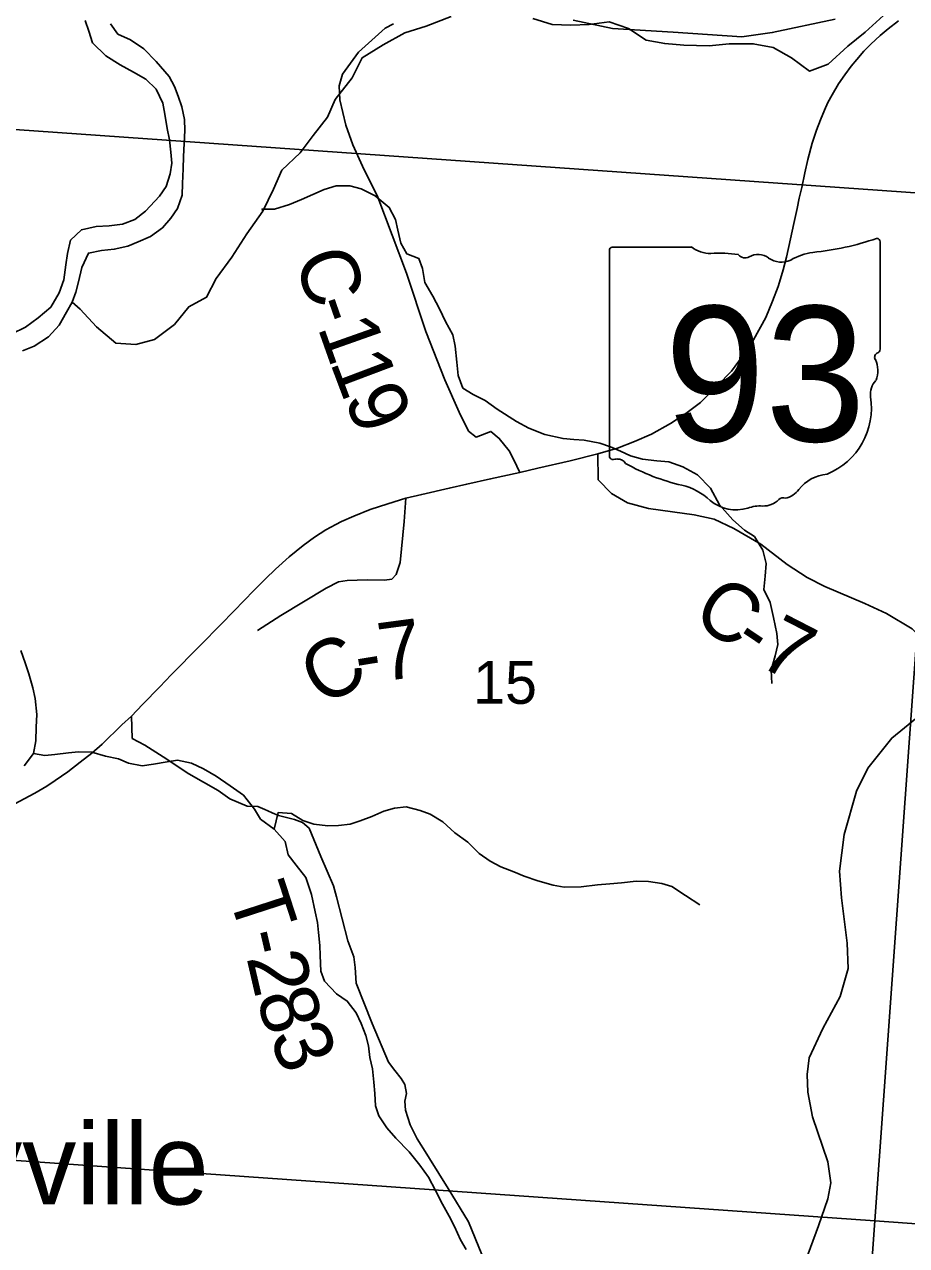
# Model space of a CAD drawing. Extents: x 0 to 34, y 0 to 22.
# Drawn here: x 3.78 to 4.64, y 16.363 to 17.554 of the extents above; entities that cross this region are included whole.
import ezdxf

# ---------------------------------------------------------------- set-up
doc = ezdxf.new("R2010")
doc.units = 0
for name, color, linetype in [('GM_X_Corporation', 7, 'Continuous'), ('GM_X_County_Road', 7, 'Continuous'), ('GM_X_County_Road_Text', 7, 'Continuous'), ('GM_X_Major_River', 7, 'Continuous'), ('GM_X_Minor_River', 7, 'Continuous'), ('GM_X_Section_Text', 7, 'Continuous'), ('GM_X_State_Location', 7, 'Continuous'), ('GM_X_State_Route', 7, 'Continuous'), ('GM_X_State_Shield', 7, 'Continuous'), ('GM_X_Township_Road', 7, 'Continuous'), ('GM_X_Township_Road_Text', 7, 'Continuous'), ('GM_X_Unincorporated_Text', 7, 'Continuous')]:
    doc.layers.add(name, color=color, linetype=linetype)

msp = doc.modelspace()

# ---------------------------------------------------------------- linework, layer by layer
at = {"layer": 'GM_X_Corporation'}
for points in [[(4.7598, 18.4308), (4.6804, 17.3872), (3.6641, 17.4586), (3.742, 18.4953)], [(3.6641, 17.4586), (4.6804, 17.3872), (4.6087, 16.3871), (3.6056, 16.4577)], [(4.6804, 17.3872), (5.6845, 17.321), (5.612, 16.3148), (5.6072, 16.3154), (4.6087, 16.3871)], [(4.6087, 16.3871), (4.5353, 15.3628), (3.5455, 15.4266), (3.6056, 16.4577)], [(4.6087, 16.3871), (5.6072, 16.3154), (5.5415, 15.2956), (4.5353, 15.3628)]]:
    msp.add_lwpolyline(points, close=True, dxfattribs=at)
at = {"layer": 'GM_X_County_Road'}
for points in [[(4.2627, 17.1168), (4.257, 17.1291), (4.2524, 17.1378), (4.2427, 17.15), (4.2346, 17.1567), (4.2201, 17.1513), (4.2127, 17.1571), (4.2036, 17.1755), (4.1895, 17.207), (4.1712, 17.2541), (4.1524, 17.3111), (4.1244, 17.385), (4.1095, 17.4154), (4.1001, 17.4361), (4.093, 17.4552), (4.0874, 17.48), (4.0866, 17.4937), (4.0899, 17.5051), (4.1055, 17.5264), (4.1314, 17.5498), (4.1395, 17.554)], [(4.3146, 17.5577), (4.3531, 17.5497), (4.4121, 17.5461), (4.4791, 17.5413), (4.5087, 17.5456), (4.57, 17.5588)], [(4.2627, 17.1168), (4.2802, 17.1208), (4.3117, 17.128), (4.3389, 17.135)], [(4.3389, 17.135), (4.339, 17.1096), (4.352, 17.0964), (4.3677, 17.087), (4.388, 17.0816), (4.4115, 17.0785), (4.4326, 17.0754), (4.4522, 17.0712), (4.4713, 17.062), (4.4975, 17.0467), (4.5233, 17.0271), (4.5427, 17.0142), (4.5599, 17.0055), (4.599, 16.9891), (4.62, 16.9791), (4.6451, 16.9642), (4.6614, 16.9475), (4.6713, 16.9325), (4.6755, 16.9179), (4.681, 16.9095), (4.6884, 16.9017), (4.6965, 16.8937)], [(4.1518, 17.0918), (4.1671, 17.0954), (4.194, 17.1014), (4.211, 17.1054), (4.2342, 17.1105), (4.2627, 17.1168)], [(4.0072, 16.9628), (4.0299, 16.9772), (4.0741, 17.0039), (4.086, 17.0102), (4.0943, 17.0115), (4.1141, 17.0122), (4.1307, 17.0119), (4.1379, 17.0128), (4.1422, 17.0173), (4.1462, 17.029), (4.1501, 17.0688), (4.1518, 17.0918)]]:
    msp.add_lwpolyline(points, dxfattribs=at)
at = {"layer": 'GM_X_Major_River'}
for points in [[(3.8392, 17.5575), (3.8426, 17.5469), (3.8464, 17.5355), (3.8592, 17.523), (3.8732, 17.5143), (3.8861, 17.5071), (3.8982, 17.5002), (3.9084, 17.4904), (3.9148, 17.4767), (3.9167, 17.4661), (3.919, 17.4521), (3.9212, 17.441), (3.9227, 17.4289), (3.9235, 17.4183), (3.922, 17.408), (3.9182, 17.3955), (3.9114, 17.386), (3.8978, 17.3716), (3.8876, 17.3632), (3.8755, 17.3587), (3.8626, 17.3571), (3.8498, 17.3564), (3.8354, 17.3533), (3.8248, 17.3431), (3.8218, 17.3302), (3.8203, 17.3192), (3.8184, 17.3047), (3.8138, 17.2918), (3.8055, 17.2778), (3.7934, 17.2675), (3.781, 17.2584), (3.7677, 17.252)], [(3.7779, 17.2353), (3.7893, 17.2398), (3.8033, 17.249), (3.8138, 17.2603), (3.821, 17.2729), (3.8263, 17.2827), (3.8301, 17.2926), (3.8327, 17.3025), (3.8358, 17.3165), (3.8422, 17.3306), (3.8551, 17.3332), (3.8675, 17.3344), (3.8808, 17.3374), (3.8906, 17.3416), (3.9027, 17.3469), (3.9144, 17.3553), (3.9227, 17.3648), (3.9292, 17.3742), (3.9337, 17.3872), (3.9341, 17.3985), (3.9345, 17.4126), (3.9348, 17.4247), (3.9356, 17.4373), (3.9363, 17.4502), (3.936, 17.4608), (3.9333, 17.4733), (3.9299, 17.4836), (3.9261, 17.4931), (3.9209, 17.5029), (3.9084, 17.5173), (3.8963, 17.5299), (3.8834, 17.5386), (3.871, 17.5439), (3.8638, 17.5541)], [(3.7797, 16.8308), (3.7888, 16.8429), (3.7911, 16.8551), (3.7915, 16.8684), (3.7919, 16.8809), (3.7903, 16.8964), (3.7881, 16.9067), (3.7843, 16.9203), (3.7805, 16.931), (3.7764, 16.9431)]]:
    msp.add_lwpolyline(points, dxfattribs=at)
at = {"layer": 'GM_X_Minor_River'}
for points in [[(4.1959, 17.5612), (4.1716, 17.5517), (4.1508, 17.5453), (4.1296, 17.5335), (4.1091, 17.521), (4.0992, 17.5016)], [(4.6172, 17.5623), (4.5994, 17.546), (4.5823, 17.5323), (4.5634, 17.5148), (4.5452, 17.508), (4.5274, 17.5209), (4.5096, 17.5312), (4.4903, 17.5347), (4.4669, 17.5347), (4.4472, 17.5328), (4.4226, 17.5332), (4.404, 17.5348), (4.3859, 17.5382), (4.3685, 17.5496), (4.3499, 17.5561), (4.3303, 17.5535), (4.3125, 17.5527), (4.2943, 17.5535), (4.2754, 17.5592)], [(4.0992, 17.5016), (4.0829, 17.4803), (4.0753, 17.4632), (4.0612, 17.4453), (4.0487, 17.4282), (4.0309, 17.4114), (4.0225, 17.3928), (4.0122, 17.3715), (3.9967, 17.3494), (3.9822, 17.3266), (3.9667, 17.3057), (3.9575, 17.2875), (3.9401, 17.2783), (3.9261, 17.2609), (3.9067, 17.2464), (3.8885, 17.2415), (3.8689, 17.2427), (3.85, 17.2587), (3.8341, 17.2758), (3.8263, 17.2827)], [(4.0122, 17.3715), (4.0116, 17.3735), (4.0237, 17.3735), (4.0384, 17.3781), (4.0501, 17.3827), (4.072, 17.3925), (4.0838, 17.3963), (4.097, 17.3963), (4.108, 17.3933), (4.1219, 17.3865), (4.1355, 17.3751), (4.1416, 17.3633), (4.1439, 17.3531), (4.1469, 17.3402), (4.1525, 17.3299), (4.1643, 17.3254), (4.168, 17.3155), (4.1703, 17.3019), (4.1779, 17.2886), (4.1843, 17.2764), (4.1903, 17.2639), (4.1975, 17.251), (4.1998, 17.24), (4.2013, 17.2244), (4.2028, 17.2112), (4.2073, 17.199), (4.2172, 17.1926), (4.2289, 17.1869), (4.2406, 17.1785), (4.2595, 17.1664), (4.2716, 17.16), (4.2871, 17.1539), (4.3049, 17.1497), (4.3154, 17.149), (4.3256, 17.1482), (4.3408, 17.1452), (4.351, 17.1418), (4.3608, 17.1376), (4.3706, 17.1331), (4.3823, 17.1296), (4.3963, 17.1281), (4.408, 17.127), (4.4216, 17.1221), (4.436, 17.1145), (4.4485, 17.1016), (4.4572, 17.0853), (4.4704, 17.0705), (4.4817, 17.0606), (4.4916, 17.0542), (4.4995, 17.0409), (4.5029, 17.028), (4.5018, 17.0155), (4.5006, 17.0026), (4.5067, 16.9901), (4.5101, 16.9753), (4.5131, 16.9597), (4.5142, 16.9491), (4.5116, 16.9381), (4.5078, 16.924), (4.5082, 16.9111)], [(3.7888, 16.8429), (3.7998, 16.8407), (3.8096, 16.8418), (3.8228, 16.8433), (3.8327, 16.8445), (3.8455, 16.8441), (3.8588, 16.8403), (3.8716, 16.8377), (3.8814, 16.8335), (3.8947, 16.8308), (3.9056, 16.8324), (3.9189, 16.8346), (3.9291, 16.8362), (3.9427, 16.8335), (3.9544, 16.8278), (3.9669, 16.8206), (3.9805, 16.8111), (3.9933, 16.802), (4.0043, 16.7884), (4.0099, 16.7789), (4.0232, 16.7691), (4.0341, 16.7569), (4.0368, 16.744), (4.0447, 16.7338), (4.0542, 16.722), (4.0598, 16.7053), (4.0632, 16.6883), (4.0655, 16.678), (4.0666, 16.6682), (4.0678, 16.6556), (4.0681, 16.6458), (4.0689, 16.6306), (4.0723, 16.6208), (4.084, 16.6086), (4.0946, 16.6014), (4.1033, 16.59), (4.1082, 16.5794), (4.1127, 16.568), (4.1154, 16.5578), (4.1165, 16.5464), (4.1191, 16.5354), (4.1206, 16.5225), (4.1214, 16.5112), (4.1222, 16.4994), (4.1252, 16.4895), (4.1331, 16.4778), (4.1418, 16.4679), (4.155, 16.4543), (4.1652, 16.4414), (4.1736, 16.4296), (4.1807, 16.4167), (4.1875, 16.4035), (4.194, 16.3917), (4.1992, 16.3815), (4.2049, 16.3686), (4.2106, 16.3591)], [(3.7888, 16.8429), (3.7888, 16.8433)], [(4.0232, 16.7691), (4.0273, 16.7854), (4.0402, 16.7842), (4.0511, 16.7774), (4.0621, 16.774), (4.0757, 16.7721), (4.0859, 16.7725), (4.0973, 16.774), (4.1071, 16.7771), (4.1184, 16.7812), (4.1301, 16.7866), (4.1407, 16.7896), (4.1521, 16.7907), (4.1657, 16.7873), (4.1755, 16.7835), (4.1876, 16.7763), (4.1993, 16.7653), (4.2122, 16.7562), (4.2231, 16.7452), (4.2337, 16.7377), (4.2443, 16.7323), (4.2568, 16.7274), (4.267, 16.7233), (4.2802, 16.7187), (4.2953, 16.7145), (4.3059, 16.7126), (4.3225, 16.7127), (4.3384, 16.7146), (4.3505, 16.7157), (4.3619, 16.7168), (4.3762, 16.7184), (4.3883, 16.718), (4.4012, 16.7161), (4.411, 16.7131), (4.4242, 16.7044), (4.4382, 16.6953)]]:
    msp.add_lwpolyline(points, dxfattribs=at)
at = {"layer": 'GM_X_State_Route'}
for points in [[(4.5147, 17.2991), (4.5193, 17.3144), (4.5225, 17.3266), (4.5265, 17.3444), (4.5297, 17.3594), (4.5332, 17.3742), (4.5351, 17.3842), (4.5375, 17.3946), (4.5405, 17.4088), (4.5436, 17.4217), (4.5477, 17.4379), (4.5518, 17.4503), (4.5558, 17.4606), (4.5597, 17.47), (4.5629, 17.4775), (4.5672, 17.485), (4.5734, 17.4957), (4.5794, 17.5044), (4.5856, 17.5129), (4.5912, 17.5195), (4.5981, 17.5275), (4.6048, 17.5342), (4.614, 17.5426), (4.6216, 17.5491), (4.6318, 17.557)], [(4.3389, 17.135), (4.358, 17.1405), (4.3745, 17.1468), (4.3912, 17.1542), (4.4097, 17.1645), (4.4246, 17.1742), (4.4389, 17.1851), (4.4555, 17.2014), (4.4689, 17.2154), (4.4823, 17.2336), (4.4905, 17.2462), (4.5024, 17.2679), (4.509, 17.2837), (4.5144, 17.2981), (4.5147, 17.2991)], [(4.2627, 17.1168), (4.2802, 17.1208), (4.3117, 17.128), (4.3389, 17.135)], [(4.1518, 17.0918), (4.1671, 17.0954), (4.194, 17.1014), (4.211, 17.1054), (4.2342, 17.1105), (4.2627, 17.1168)], [(3.7698, 16.7933), (3.7899, 16.8041), (3.8016, 16.811), (3.81, 16.8166), (3.8221, 16.8249), (3.8343, 16.8342), (3.8455, 16.8431), (3.8557, 16.852), (3.875, 16.8707), (3.8843, 16.8792), (3.8949, 16.8904), (3.9118, 16.9078), (3.923, 16.9193), (3.9507, 16.9477), (3.9719, 16.9693), (3.9948, 16.9927), (4.0029, 17.0011), (4.0148, 17.0131), (4.0247, 17.0226), (4.0378, 17.0344), (4.0517, 17.0456), (4.0625, 17.0538), (4.0738, 17.0608), (4.0834, 17.0661), (4.089, 17.0689), (4.1011, 17.0743), (4.117, 17.0807), (4.1341, 17.0862), (4.1518, 17.0918)], [(4.5384, 16.34), (4.5538, 16.3822), (4.563, 16.4086), (4.5659, 16.4241), (4.5628, 16.4446), (4.548, 16.4885), (4.5435, 16.5125), (4.5427, 16.5299), (4.5448, 16.5462), (4.5582, 16.5748), (4.575, 16.606), (4.5826, 16.6332), (4.5819, 16.6579), (4.5762, 16.702), (4.5743, 16.7282), (4.5787, 16.7637), (4.5908, 16.806), (4.6018, 16.8286), (4.6253, 16.8578), (4.6537, 16.8809), (4.6682, 16.8882), (4.6965, 16.8937)]]:
    msp.add_lwpolyline(points, dxfattribs=at)
at = {"layer": 'GM_X_State_Shield'}
for p, q in [((4.43, 17.3365), (4.3528, 17.3365)), ((4.6138, 17.2368), (4.6138, 17.3415)), ((4.3502, 17.3331), (4.3502, 17.133)), ((4.6138, 17.2368), (4.6138, 17.2368))]:
    msp.add_line(p, q, dxfattribs=at)
for centre, radius, start, end in [((4.3532, 17.3335), 0.00305, 98.1301, 188.1301), ((4.4484, 17.3598), 0.0296, 231.6195, 271.1119), ((4.5199, 17.6094), 0.2796, 275.8445, 288.9065), ((4.6109, 17.3419), 0.00294, 351.8621, 97.738), ((4.4582, 17.2242), 0.1064, 80.4867, 94.9883), ((4.4823, 17.3345), 0.00855, 219.7921, 297.1024), ((4.4949, 17.3114), 0.0178, 54.4667, 119.1411), ((4.5178, 17.3431), 0.0214, 233.8562, 294.8282), ((4.5556, 17.2754), 0.0563, 97.3462, 120.7689), ((4.6131, 17.2291), 0.00454, 107.944, 210.337), ((4.5843, 17.2159), 0.0273, 340.033, 23.6496), ((4.6107, 17.2364), 0.00314, 289.6038, 7.7341), ((4.6243, 17.193), 0.0198, 136.8065, 186.9296), ((4.5356, 17.1797), 0.0699, 292.3089, 8.9858), ((4.3532, 17.1325), 0.00308, 171.9584, 258.3066), ((4.3537, 17.153), 0.0235, 267.339, 280.6039), ((4.3585, 17.1214), 0.00848, 29.7484, 93.2717), ((4.4655, 17.3012), 0.2019, 240.4129, 257.1985), ((4.5651, 17.0768), 0.0383, 94.4031, 142.5768), ((4.4053, 17.0431), 0.0632, 47.1842, 75.836), ((4.5165, 17.1136), 0.0226, 282.8732, 323.2771), ((4.4737, 17.1204), 0.0401, 230.7004, 286.2918), ((4.4968, 17.0512), 0.0329, 85.6951, 111.2099), ((4.4998, 17.1054), 0.0214, 268.777, 315.5493), ((4.5191, 17.0861), 0.00601, 65.7517, 132.6484)]:
    msp.add_arc(centre, radius, start, end, dxfattribs=at)
at = {"layer": 'GM_X_Township_Road'}
for points in [[(3.8843, 16.8792), (3.8848, 16.8575), (3.8972, 16.8508), (3.9151, 16.8394), (3.9402, 16.823), (3.9686, 16.8068), (3.9802, 16.7986), (3.9971, 16.7914), (4.0073, 16.7912), (4.0141, 16.7881)], [(4.0141, 16.7881), (4.0171, 16.7868), (4.0215, 16.785), (4.0276, 16.7824), (4.043, 16.7783), (4.0509, 16.7754), (4.0573, 16.77), (4.0688, 16.7424), (4.081, 16.7137), (4.0842, 16.703), (4.095, 16.6602), (4.1008, 16.6445), (4.1024, 16.6342), (4.1032, 16.619), (4.1187, 16.5796), (4.1349, 16.5417), (4.1408, 16.5336), (4.1471, 16.5258), (4.1507, 16.5201), (4.1524, 16.5113), (4.1508, 16.5037), (4.1513, 16.495), (4.1559, 16.4809), (4.1628, 16.467), (4.172, 16.4522)], [(4.172, 16.4522), (4.1747, 16.4478), (4.1929, 16.4186), (4.2126, 16.3863), (4.2256, 16.3545), (4.2435, 16.3271), (4.2652, 16.2933), (4.2848, 16.2716), (4.3019, 16.2553), (4.3158, 16.2349), (4.3204, 16.2207), (4.3172, 16.209), (4.3177, 16.2003), (4.3243, 16.1909)]]:
    msp.add_lwpolyline(points, dxfattribs=at)

# ---------------------------------------------------------------- texts
at = {"layer": 'GM_X_County_Road_Text'}
for s, rotation, p in [('C', 289.1308, (4.0422, 17.325)), ('-', 289.1996, (4.0575, 17.2808)), ('1', 289.4769, (4.0653, 17.2585)), ('1', 290.6915, (4.0774, 17.2243)), ('9', 293.1822, (4.0908, 17.189)), ('C', 325.3351, (4.4284, 16.9734)), ('7', 332.7624, (4.4931, 16.9297)), ('7', 7.6175, (4.1284, 16.913)), ('-', 326.0871, (4.4675, 16.9464)), ('C', 30.7029, (4.0709, 16.8874)), ('-', 9.1916, (4.1058, 16.9094))]:
    msp.add_text(s, height=0.0568, rotation=rotation, dxfattribs=at).set_placement(p)
at = {"layer": 'GM_X_Section_Text'}
msp.add_text('15', height=0.04186, rotation=0, dxfattribs=at).set_placement((4.2172, 16.8912))
at = {"layer": 'GM_X_State_Location'}
for s in ['s', 'r']:
    msp.add_text(s, height=0.000189, dxfattribs=at).set_placement((4.479, 17.2197))
msp.add_text('93', height=0.000189, rotation=0, dxfattribs=at).set_placement((4.4313, 17.2059))
at = {"layer": 'GM_X_State_Shield'}
msp.add_text('93', height=0.13184, dxfattribs=at).set_placement((4.4038, 17.1471))
at = {"layer": 'GM_X_Township_Road_Text'}
for s, rotation, p in [('T', 287.9894, (3.9781, 16.7059)), ('-', 283.127, (3.9909, 16.6667)), ('2', 283.023, (3.9962, 16.644)), ('8', 287.3483, (4.0053, 16.6053)), ('3', 292.8918, (4.0178, 16.5663))]:
    msp.add_text(s, height=0.0568, rotation=rotation, dxfattribs=at).set_placement(p)
at = {"layer": 'GM_X_Unincorporated_Text'}
msp.add_text('Coryville', height=0.07898, rotation=0, dxfattribs=at).set_placement((3.5547, 16.4031))

doc.saveas('drawing.dxf')
